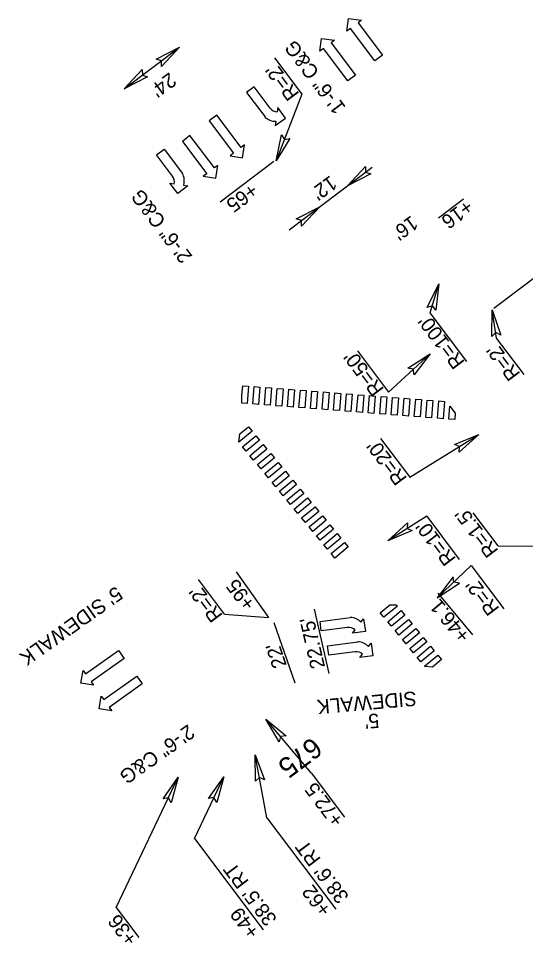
# Model space of a CAD drawing. Extents: x 1262692 to 1264138, y 775643 to 777474.
# Drawn here: x 1263203.8 to 1263379.2, y 776386.7 to 776704.8 of the extents above; entities that cross this region are included whole.
import ezdxf

# ---------------------------------------------------------------- set-up
doc = ezdxf.new("R2010")
doc.units = 0
for name, color, linetype in [('Prop Dimension', 7, 'Continuous'), ('Prop Dimension Text', 7, 'Continuous'), ('Prop Horizontal Alignment Tick Label', 7, 'Continuous'), ('Prop Lane Arrow CELL', 7, 'Continuous'), ('Prop Mkg Solid White Crosswalks', 7, 'Continuous'), ('Prop Terminator CELL', 7, 'Continuous')]:
    doc.layers.add(name, color=color, linetype=linetype)

msp = doc.modelspace()

# ---------------------------------------------------------------- linework, layer by layer
at = {"layer": 'Prop Dimension'}
for p, q in [((1263240.33, 776680.45), (1263259.51, 776694.89)), ((1263297.42, 776631.75), (1263326.1, 776653.35)), ((1263349, 776635.87), (1263357.73, 776642.45)), ((1263368.14, 776604.63), (1263384.56, 776617)), ((1263358.84, 776586.13), (1263346.16, 776602.96)), ((1263378.63, 776581.74), (1263369.14, 776594.22))]:
    msp.add_line(p, q, dxfattribs=at)
at = {"layer": 'Prop Dimension Text'}
for p, q in [((1263292.35, 776691.09), (1263301.8, 776678.54)), ((1263301.8, 776678.54), (1263292.88, 776655.51)), ((1263292.15, 776655.28), (1263273.58, 776641.29)), ((1263369.14, 776594.22), (1263367.64, 776604.01)), ((1263329.02, 776559.56), (1263339.09, 776546.19)), ((1263339.09, 776546.19), (1263363.01, 776560.96)), ((1263369.67, 776522.44), (1263361.01, 776533.86)), ((1263344.96, 776532.7), (1263331.54, 776524.25)), ((1263344.96, 776532.7), (1263356.22, 776517.75)), ((1263369.67, 776522.44), (1263391.79, 776522.29)), ((1263348.57, 776504.5), (1263360.38, 776515.64)), ((1263360.38, 776515.64), (1263371.63, 776500.7)), ((1263279.08, 776513.48), (1263290.23, 776497.73)), ((1263275.05, 776498.91), (1263266.01, 776510.82)), ((1263348.83, 776506.12), (1263360.81, 776491.68)), ((1263275.05, 776498.91), (1263290.25, 776497.75)), ((1263311.19, 776478.4), (1263306.14, 776500.59)), ((1263299.43, 776475.03), (1263292.2, 776495.81)), ((1263305.02, 776444.03), (1263289.32, 776462.61)), ((1263289.71, 776428.49), (1263285.7, 776450.22)), ((1263305.02, 776444.03), (1263316.54, 776428.74)), ((1263289.71, 776428.49), (1263313.49, 776396.92)), ((1263264.63, 776421.31), (1263288.41, 776389.75)), ((1263237.63, 776397.41), (1263245.4, 776387.1))]:
    msp.add_line(p, q, dxfattribs=at)
for points in [[(1263346.16, 776602.96), (1263349.19, 776613.04)], [(1263320.99, 776589.87), (1263331.72, 776575.62), (1263346.15, 776588.87)], [(1263237.63, 776397.41), (1263259.07, 776442.56)], [(1263264.63, 776421.31), (1263274.76, 776442.64)]]:
    msp.add_lwpolyline(points, dxfattribs=at)
at = {"layer": 'Prop Lane Arrow CELL'}
for p, q in [((1263317.39, 776700.39), (1263317.97, 776704.78)), ((1263317.97, 776704.78), (1263322.42, 776704.18)), ((1263322.42, 776704.18), (1263321.22, 776703.28)), ((1263321.22, 776703.28), (1263329.64, 776692.1)), ((1263318.58, 776701.3), (1263317.39, 776700.39)), ((1263327.01, 776690.11), (1263318.58, 776701.3)), ((1263308.04, 776693.45), (1263308.62, 776697.84)), ((1263308.62, 776697.84), (1263313.07, 776697.24)), ((1263313.07, 776697.24), (1263311.87, 776696.34)), ((1263311.87, 776696.34), (1263320.3, 776685.16)), ((1263309.24, 776694.36), (1263308.04, 776693.45)), ((1263317.66, 776683.17), (1263309.24, 776694.36)), ((1263329.64, 776692.1), (1263327.01, 776690.11)), ((1263320.3, 776685.16), (1263317.66, 776683.17)), ((1263285.34, 776681.11), (1263282.7, 776679.13)), ((1263290.84, 776673.8), (1263285.34, 776681.11)), ((1263282.7, 776679.13), (1263289.05, 776670.7)), ((1263293.47, 776673.97), (1263293.27, 776672.5)), ((1263296.14, 776670.35), (1263293.47, 776673.97)), ((1263272.36, 776671.34), (1263269.72, 776669.35)), ((1263280.78, 776660.15), (1263272.36, 776671.34)), ((1263292.59, 776667.74), (1263296.14, 776670.35)), ((1263269.72, 776669.35), (1263278.14, 776658.17)), ((1263292.8, 776669.21), (1263292.59, 776667.74)), ((1263263.11, 776664.27), (1263260.47, 776662.28)), ((1263271.53, 776653.09), (1263263.11, 776664.27)), ((1263260.47, 776662.28), (1263268.89, 776651.1)), ((1263281.98, 776661.06), (1263280.78, 776660.15)), ((1263281.32, 776656.61), (1263281.98, 776661.06)), ((1263251.52, 776657.59), (1263254.15, 776659.57)), ((1263257.02, 776650.28), (1263251.52, 776657.59)), ((1263254.15, 776659.57), (1263260.5, 776651.14)), ((1263278.14, 776658.17), (1263276.95, 776657.27)), ((1263276.95, 776657.27), (1263281.32, 776656.61)), ((1263268.89, 776651.1), (1263267.69, 776650.2)), ((1263272.73, 776653.99), (1263271.53, 776653.09)), ((1263272.07, 776649.55), (1263272.73, 776653.99)), ((1263267.69, 776650.2), (1263272.07, 776649.55)), ((1263258.88, 776644.23), (1263256.14, 776647.8)), ((1263256.14, 776647.8), (1263257.61, 776647.59)), ((1263262.37, 776646.92), (1263258.88, 776644.23)), ((1263260.9, 776647.13), (1263262.37, 776646.92)), ((1263308.07, 776496.33), (1263318.53, 776497.68)), ((1263308.49, 776493.06), (1263308.07, 776496.33)), ((1263322.22, 776496.04), (1263323.13, 776497.22)), ((1263323.13, 776497.22), (1263323.74, 776492.86)), ((1263317.57, 776494.23), (1263308.49, 776493.06)), ((1263319.29, 776492.23), (1263320.2, 776493.41)), ((1263323.74, 776492.86), (1263319.29, 776492.23)), ((1263310.64, 776487.93), (1263321.1, 776489.28)), ((1263227, 776478.18), (1263238.42, 776486.27)), ((1263238.42, 776486.27), (1263240.33, 776483.58)), ((1263311.06, 776484.66), (1263310.64, 776487.93)), ((1263320.14, 776485.83), (1263311.06, 776484.66)), ((1263324.79, 776487.64), (1263325.7, 776488.82)), ((1263325.7, 776488.82), (1263326.31, 776484.46)), ((1263240.33, 776483.58), (1263228.9, 776475.49)), ((1263321.86, 776483.83), (1263322.77, 776485.01)), ((1263326.31, 776484.46), (1263321.86, 776483.83)), ((1263225.41, 776474.98), (1263226.13, 776479.41)), ((1263226.13, 776479.41), (1263227, 776478.18)), ((1263233.26, 776469.33), (1263244.69, 776477.42)), ((1263244.69, 776477.42), (1263246.6, 776474.72)), ((1263229.77, 776474.27), (1263225.41, 776474.98)), ((1263228.9, 776475.49), (1263229.77, 776474.27)), ((1263246.6, 776474.72), (1263235.17, 776466.63)), ((1263231.67, 776466.12), (1263232.4, 776470.55)), ((1263232.4, 776470.55), (1263233.26, 776469.33)), ((1263235.17, 776466.63), (1263236.04, 776465.41)), ((1263236.04, 776465.41), (1263231.67, 776466.12))]:
    msp.add_line(p, q, dxfattribs=at)
for centre, radius, start, end in [((1263293.45, 776675.76), 3.27, 216.9874, 266.6456), ((1263292.71, 776674.45), 5.25, 225.6635, 270.9752), ((1263255.89, 776648.66), 5.25, 342.9996, 28.3113), ((1263254.43, 776648.31), 3.27, 347.3292, 36.9874), ((1263318.41, 776492.45), 5.25, 43.3725, 88.6841), ((1263318, 776491), 3.27, 47.702, 97.3602), ((1263320.98, 776484.05), 5.25, 43.3725, 88.6841), ((1263320.57, 776482.6), 3.27, 47.702, 97.3602)]:
    msp.add_arc(centre, radius, start, end, dxfattribs=at)
at = {"layer": 'Prop Mkg Solid White Crosswalks'}
for points in [[(1263282.86, 776571.69), (1263281.07, 776571.83), (1263281.07, 776574.45), (1263281.33, 776577.83), (1263283.32, 776577.67)], [(1263285.32, 776577.52), (1263287.31, 776577.36), (1263286.84, 776571.38), (1263284.85, 776571.53)], [(1263289.31, 776577.21), (1263291.3, 776577.05), (1263290.83, 776571.07), (1263288.84, 776571.22)], [(1263293.29, 776576.89), (1263295.29, 776576.74), (1263294.82, 776570.76), (1263292.83, 776570.91)], [(1263297.28, 776576.58), (1263299.27, 776576.43), (1263298.81, 776570.45), (1263296.81, 776570.6)], [(1263301.27, 776576.27), (1263303.26, 776576.12), (1263302.8, 776570.14), (1263300.8, 776570.29)], [(1263305.26, 776575.96), (1263307.25, 776575.81), (1263306.78, 776569.82), (1263304.79, 776569.98)], [(1263309.24, 776575.65), (1263311.24, 776575.5), (1263310.77, 776569.51), (1263308.78, 776569.67)], [(1263313.23, 776575.34), (1263315.23, 776575.18), (1263314.76, 776569.2), (1263312.77, 776569.36)], [(1263317.22, 776575.03), (1263319.21, 776574.87), (1263318.75, 776568.89), (1263316.75, 776569.05)], [(1263321.21, 776574.72), (1263323.2, 776574.56), (1263322.74, 776568.58), (1263320.74, 776568.74)], [(1263325.2, 776574.41), (1263327.19, 776574.25), (1263326.72, 776568.27), (1263324.73, 776568.43)], [(1263329.18, 776574.1), (1263331.18, 776573.94), (1263330.71, 776567.96), (1263328.72, 776568.11)], [(1263333.17, 776573.79), (1263335.17, 776573.63), (1263334.7, 776567.65), (1263332.71, 776567.8)], [(1263337.16, 776573.47), (1263339.15, 776573.32), (1263338.69, 776567.34), (1263336.69, 776567.49)], [(1263341.15, 776573.16), (1263343.14, 776573.01), (1263342.68, 776567.03), (1263340.68, 776567.18)], [(1263345.14, 776572.85), (1263347.13, 776572.7), (1263346.66, 776566.72), (1263344.67, 776566.87)], [(1263349.12, 776572.54), (1263351.12, 776572.39), (1263350.65, 776566.4), (1263348.66, 776566.56)], [(1263354.81, 776568.35), (1263354.64, 776566.09), (1263352.65, 776566.25), (1263353, 776570.76)], [(1263283.34, 776563.62), (1263284.61, 776562.08), (1263280, 776558.25), (1263279.99, 776558.26), (1263280.38, 776561.17)], [(1263285.89, 776560.54), (1263287.17, 776559), (1263282.55, 776555.17), (1263281.27, 776556.71)], [(1263288.44, 776557.47), (1263289.72, 776555.93), (1263285.1, 776552.09), (1263283.83, 776553.63)], [(1263291.01, 776554.4), (1263292.29, 776552.86), (1263287.67, 776549.03), (1263286.4, 776550.57)], [(1263293.57, 776551.32), (1263294.84, 776549.78), (1263290.23, 776545.95), (1263288.95, 776547.49)], [(1263296.12, 776548.24), (1263297.4, 776546.7), (1263292.78, 776542.87), (1263291.5, 776544.41)], [(1263298.68, 776545.16), (1263299.95, 776543.62), (1263295.33, 776539.79), (1263294.06, 776541.33)], [(1263301.23, 776542.08), (1263302.51, 776540.55), (1263297.89, 776536.71), (1263296.61, 776538.25)], [(1263303.78, 776539.01), (1263305.06, 776537.47), (1263300.44, 776533.64), (1263299.17, 776535.18)], [(1263306.34, 776535.93), (1263307.61, 776534.39), (1263303, 776530.56), (1263301.72, 776532.1)], [(1263308.89, 776532.85), (1263310.17, 776531.31), (1263305.55, 776527.48), (1263304.27, 776529.02)], [(1263311.45, 776529.77), (1263312.72, 776528.23), (1263308.1, 776524.4), (1263306.83, 776525.94)], [(1263314, 776526.69), (1263315.28, 776525.15), (1263310.66, 776521.32), (1263309.38, 776522.86)], [(1263316.55, 776523.61), (1263317.83, 776522.07), (1263313.21, 776518.24), (1263311.94, 776519.78)], [(1263332.25, 776502.09), (1263334.38, 776502.13), (1263334.81, 776501.61), (1263330.19, 776497.78), (1263328.92, 776499.32)], [(1263336.09, 776500.08), (1263337.36, 776498.54), (1263332.75, 776494.71), (1263331.47, 776496.24)], [(1263338.64, 776497), (1263339.92, 776495.46), (1263335.3, 776491.63), (1263334.02, 776493.17)], [(1263341.2, 776493.92), (1263342.47, 776492.38), (1263337.85, 776488.55), (1263336.58, 776490.09)], [(1263343.75, 776490.84), (1263345.03, 776489.3), (1263340.41, 776485.47), (1263339.13, 776487.01)], [(1263346.3, 776487.76), (1263347.58, 776486.22), (1263342.96, 776482.39), (1263341.69, 776483.93)], [(1263348.86, 776484.68), (1263350.13, 776483.14), (1263347.01, 776480.55), (1263344.28, 776480.8), (1263344.24, 776480.85)]]:
    msp.add_lwpolyline(points, close=True, dxfattribs=at)
at = {"layer": 'Prop Terminator CELL'}
for points in [[(1263251.38, 776690.71), (1263259.51, 776694.89), (1263253.24, 776688.17), (1263253.2, 776690.14)], [(1263248.46, 776684.63), (1263240.33, 776680.45), (1263246.6, 776687.17), (1263246.64, 776685.2)], [(1263297.61, 776663.32), (1263292.88, 776655.51), (1263294.7, 776664.52), (1263295.76, 776662.87)], [(1263325.66, 776651.07), (1263317.54, 776646.89), (1263323.8, 776653.62), (1263323.85, 776651.65)], [(1263299.85, 776635.51), (1263307.97, 776639.69), (1263301.7, 776632.96), (1263301.66, 776634.93)], [(1263345.11, 776604.87), (1263349.19, 776613.04), (1263348.12, 776603.91), (1263346.91, 776605.47)], [(1263367.45, 776594.88), (1263367.64, 776604.01), (1263370.57, 776595.29), (1263368.82, 776596.19)], [(1263338.48, 776583.93), (1263346.15, 776588.87), (1263340.57, 776581.57), (1263340.33, 776583.53)], [(1263354.53, 776557.55), (1263363.01, 776560.96), (1263356.15, 776554.84), (1263356.28, 776556.81)], [(1263339.96, 776527.8), (1263331.54, 776524.25), (1263338.3, 776530.48), (1263338.19, 776528.51)], [(1263354.08, 776511.79), (1263348.57, 776504.5), (1263356.27, 776509.52), (1263354.34, 776509.9)], [(1263293.97, 776454.74), (1263289.32, 776462.61), (1263296.4, 776456.75), (1263294.44, 776456.59)], [(1263285.76, 776441.08), (1263285.7, 776450.22), (1263288.87, 776441.59), (1263287.09, 776442.44)], [(1263253.83, 776435.08), (1263259.07, 776442.56), (1263256.65, 776433.69), (1263255.7, 776435.41)], [(1263269.52, 776435.16), (1263274.76, 776442.64), (1263272.34, 776433.77), (1263271.39, 776435.49)]]:
    msp.add_lwpolyline(points, close=True, dxfattribs=at)

# ---------------------------------------------------------------- texts
at = {"layer": 'Prop Dimension Text'}
for s, rotation, p in [('1\'-6" C&G', 126.9874, (1263317.19, 776674.04)), ("24'", 216.1502, (1263256.03, 776686.31)), ("R=2'", 126.9874, (1263301.1, 776678.73)), ("12'", 216.1502, (1263311.62, 776650.71)), ('2\'-6" C&G', 126.9874, (1263264.14, 776622.57)), ('+65', 216.1502, (1263284.32, 776648.09)), ('+16', 216.1502, (1263358.74, 776642.4)), ("16'", 216.1502, (1263339.64, 776636.87)), ("R=100'", 126.9874, (1263358.37, 776585.99)), ("R=2'", 126.9874, (1263377.51, 776581.89)), ("R=50'", 126.9874, (1263330.38, 776576.61)), ("R=20'", 126.9874, (1263338.36, 776545.84)), ("R=1.5'", 126.9874, (1263369.95, 776520.81)), ("R=10'", 126.9874, (1263355.28, 776517.98)), ("5' SIDEWALK", 215.2883, (1263237.51, 776508.72)), ("R=2'", 126.9874, (1263274.66, 776498.44)), ('+95', 126.9874, (1263286.01, 776502.48)), ("R=2'", 126.9874, (1263370.31, 776500.78)), ('+46.1', 130.056, (1263360.32, 776491.6)), ("22.75'", 103.0085, (1263309.85, 776480.62)), ("22'", 108.7462, (1263296.64, 776481.17)), ('SIDEWALK', 184.9494, (1263341.23, 776472.21)), ("5' ", 184.9494, (1263328.32, 776464.59)), ('2\'-6" C&G', 215.2883, (1263262.43, 776460.95)), ('+72.5', 126.9874, (1263316.6, 776427.71)), ("38.6' RT", 126.9874, (1263318.29, 776401.25)), ("38.5' RT", 126.9874, (1263293.4, 776393.51)), ('+62', 126.9874, (1263312.3, 776396.74)), ('+49', 126.9874, (1263287.41, 776389)), ('+36', 126.9874, (1263245.18, 776386.55))]:
    msp.add_text(s, height=5, rotation=rotation, dxfattribs=at).set_placement(p)
at = {"layer": 'Prop Horizontal Alignment Tick Label'}
msp.add_text('675', height=7, rotation=216.9874, dxfattribs=at).set_placement((1263305.4, 776456.7))

doc.saveas('drawing.dxf')
